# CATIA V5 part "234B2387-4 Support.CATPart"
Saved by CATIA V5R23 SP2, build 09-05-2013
Part number: 234B2387-4 Support
Material "Sponge": density 10 kg/m3
Material "Honeycomb": density 40 kg/m3
Bounding box of the stored display mesh (mm): x 31576.209 to 31877.021, y -11276.323 to -11119.771, z 5353.147 to 5386.502
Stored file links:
  C:\Users\rem1927\Desktop\Current Explicit Composite Demo\234B2387-4 Support.CATPart
  C:\Users\rem1927\Desktop\Current Explicit Composite Demo\234B5678-1 Composite Product.CATProduct
  C:\Users\rem1927\Desktop\Current Explicit Composite Demo\234B5678_2_Rev_.CATPart
  C:\Program Files\Dassault Systemes\B23SP2PRALL\win_b64\startup\materials\sponge.jpg
  C:\Program Files\Dassault Systemes\B23SP2PRALL\win_b64\startup\materials\honeycomb.jpg
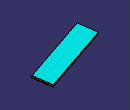
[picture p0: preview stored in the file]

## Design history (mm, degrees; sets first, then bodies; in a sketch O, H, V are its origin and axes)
WSupportSet1
AxisSystem1 "Rosette Co-Cure": origin (31531.0883, -11236.227, 5380.6358), X (-0.9552, -0.2927, 0.0445), Y (0.2961, -0.9443, 0.1435), Z (0, 0.1502, 0.9887)
Set1
  Intersect1: OnSupport {wsupport Support Plane2, RefPoint Intersect1, GridIn {cartgrid StepH1 25.4, StepH2 100, StepV1 25.4, StepV2 100, Direction DatumCurve1}}, ToIntersect1 Plane3, ToIntersect2 DatumCurve1
  Point1: type OnPlane, OnSupport {wsupport Support Plane2, RefPoint Intersect1, GridIn {cartgrid StepH1 25.4, StepH2 100, StepV1 25.4, StepV2 100, Direction DatumCurve1}}, Support Plane2, RefPoint Intersect1, H -50.8, V -2.54, Direction DatumCurve1
  Point2: type OnPlane, OnSupport {wsupport Support Plane2, RefPoint Intersect1, GridIn {cartgrid StepH1 25.4, StepH2 100, StepV1 25.4, StepV2 100, Direction DatumCurve1}}, Support Plane2, RefPoint Intersect1, H -50.8, V -76.2, Direction DatumCurve1
  Point3: type OnPlane, OnSupport {wsupport Support Plane2, RefPoint Intersect1, GridIn {cartgrid StepH1 25.4, StepH2 100, StepV1 25.4, StepV2 100, Direction DatumCurve1}}, Support Plane2, RefPoint Intersect1, H 241.3, V -2.54, Direction DatumCurve1
  Point4: type OnPlane, OnSupport {wsupport Support Plane2, RefPoint Intersect1, GridIn {cartgrid StepH1 25.4, StepH2 100, StepV1 25.4, StepV2 100, Direction DatumCurve1}}, Support Plane2, RefPoint Intersect1, H 241.3, V -76.2, Direction DatumCurve1
  Line1: type PtPt, OnSupport {wsupport Support Plane2, RefPoint Intersect1, GridIn {cartgrid StepH1 25.4, StepH2 100, StepV1 25.4, StepV2 100, Direction DatumCurve1}}, FirstPoint Point2, SecondPoint Point1, Support Plane2
  Line2: type PtPt, OnSupport {wsupport Support Plane2, RefPoint Intersect1, GridIn {cartgrid StepH1 25.4, StepH2 100, StepV1 25.4, StepV2 100, Direction DatumCurve1}}, FirstPoint Point1, SecondPoint Point3, Support Plane2
  Line3: type PtPt, OnSupport {wsupport Support Plane2, RefPoint Intersect1, GridIn {cartgrid StepH1 25.4, StepH2 100, StepV1 25.4, StepV2 100, Direction DatumCurve1}}, FirstPoint Point4, SecondPoint Point2, Support Plane2
  Line4: type PtPt, OnSupport {wsupport Support Plane2, RefPoint Intersect1, GridIn {cartgrid StepH1 25.4, StepH2 100, StepV1 25.4, StepV2 100, Direction DatumCurve1}}, FirstPoint Point3, SecondPoint Point4, Support Plane2
  Join1: Elements (Line1; Line2; Line3; Line4), OnSupport {wsupport Support Plane2, RefPoint Intersect1, GridIn {cartgrid StepH1 25.4, StepH2 100, StepV1 25.4, StepV2 100, Direction DatumCurve1}}
  Point5: type OnSurface, Support start face of Pad6, Length 45.231, Direction (-0.9964, -0.0833, 0.0127)
  Plane1: type Offset, RefPlane start face of Pad6, Offset 0, reversed
  Point6: stored without definition
Set2
  Plane2: linked copy from another document
  DatumCurve1: linked copy from another document
  Plane3: linked copy from another document
Set3 "Ply Group 1"
  Set4 "Sequence 10"
    Set5 "Ply 1"
      CLDGeom1 "Ply 1 Geometry"
  Set6 "Sequence 20"
    Set7 "Ply 2"
      CLDGeom2 "Ply 2 Geometry"
  Set8 "Sequence 30"
    Set9 "Ply 3"
      CLDGeom3 "Tessellation.1"
  Set10 "Sequence 40"
    Set11 "Ply 4"
      CLDGeom4 "Tessellation.2"
  Set12 "Sequence 50"
    Set13 "Ply 5"
      CLDGeom5 "Tessellation.3"
Set14 "Ply Group 2", material "Sponge"
  CLDGeom6 "Core Geometry"
Set15 "Ply Group 3"
  Set16 "Sequence 60"
    Set17 "Ply 6"
      CLDGeom7 "Ply 6 Geometry"
  Set18 "Sequence 70"
    Set19 "Ply 7"
      CLDGeom8 "Ply 7 Geometry"
  Set20 "Sequence 80"
    Set21 "Ply 8"
      CLDGeom9 "Ply 8 Geometry"
  Set22 "Sequence 90"
    Set23 "Ply 9"
      CLDGeom10 "Ply 9 Geometry"
  Set24 "Sequence 100"
    Set25 "Ply 10"
      CLDGeom11 "Ply 10 Geometry"
Body1 "Core" (main body), material "Honeycomb"
  Pad1: profile Join1, length 3.683, opposite side length 3.683
Body2 "Ply 1s"
  Pad2: profile Join1, length 3.683, opposite side length -3.937
Body3 "Ply 2s"
  Pad3: profile Join1, length 3.937, opposite side length -4.191
Body4 "Ply 3s"
  Pad4: profile Join1, length 4.191, opposite side length -4.445
Body5 "Ply 4s"
  Pad5: profile Join1, length 4.445, opposite side length -4.699
Body6 "Ply 5s"
  Pad6: profile Join1, length 4.699, opposite side length -4.953
Body7 "Ply 6s"
  Pad7: profile Join1, length 3.683, opposite side length -3.937
Body8 "Ply 7s"
  Pad8: profile Join1, length 3.937, opposite side length -4.191
Body9 "Ply 8s"
  Pad9: profile Join1, length 4.191, opposite side length -4.445
Body10 "Ply 9s"
  Pad10: profile Join1, length 4.445, opposite side length -4.699
Body11 "Ply 10s"
  Pad11: profile Join1, length 4.699, opposite side length -4.953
